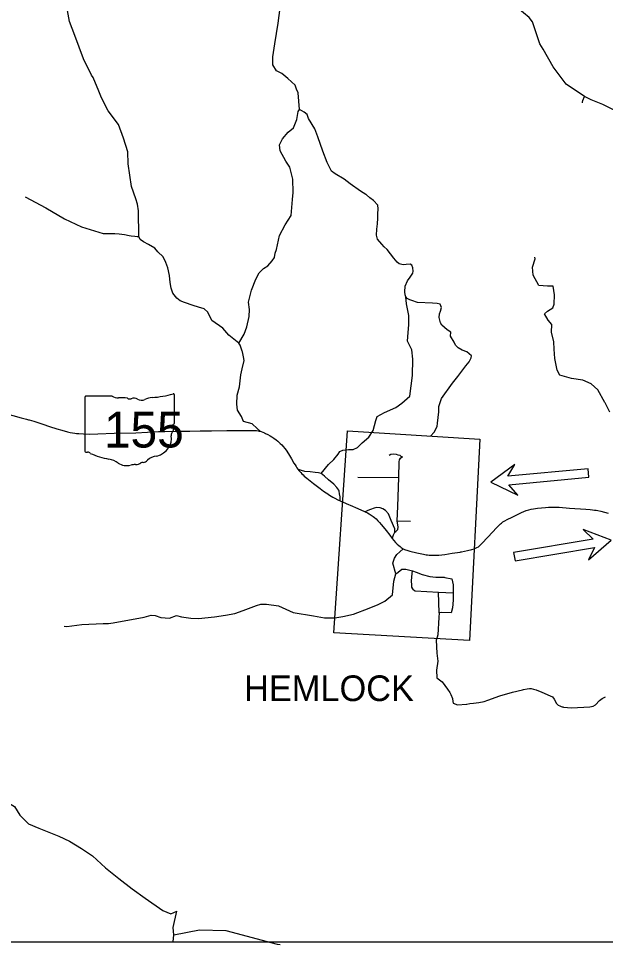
# Model space of a CAD drawing. Extents: x 2025369 to 2161369, y 549489 to 637489.
# Drawn here: x 2058249 to 2069680, y 571509 to 589545 of the extents above; entities that cross this region are included whole.
import ezdxf

# ---------------------------------------------------------------- set-up
doc = ezdxf.new("R2010")
doc.units = 0
for name, color, linetype in [('GM_X_City_Street', 7, 'Continuous'), ('GM_X_Corporation', 7, 'Continuous'), ('GM_X_Corporation_Text', 7, 'Continuous'), ('GM_X_County_Road', 7, 'Continuous'), ('GM_X_State_Route', 7, 'Continuous'), ('GM_X_State_Shield', 7, 'Continuous'), ('GM_X_Township_Road', 7, 'Continuous'), ('SH_Text', 7, 'Continuous')]:
    doc.layers.add(name, color=color, linetype=linetype)

msp = doc.modelspace()

# ---------------------------------------------------------------- linework, layer by layer
at = {"layer": 'GM_X_City_Street'}
for points in [[(2065470, 581041), (2065501, 581059), (2065553, 581067), (2065603, 581060), (2065639, 581048), (2065674, 581037), (2065696, 581020), (2065724, 581012)], [(2065581, 579541), (2065597, 579556), (2065616, 579571), (2065635, 579594), (2065644, 579640), (2065624, 579761), (2065636, 580039), (2065654, 580608), (2065664, 580911), (2065666, 580951), (2065685, 580983), (2065724, 581012)], [(2064854, 580610), (2065654, 580608)], [(2065529, 579415), (2065539, 579452), (2065553, 579489), (2065566, 579516), (2065581, 579541), (2065577, 579607), (2065505, 579770), (2065455, 579895), (2065393, 579960), (2065343, 579995), (2065294, 580016), (2065230, 580020), (2065178, 580008), (2065107, 579983), (2065051, 579962), (2065002, 579938)], [(2065624, 579761), (2065884, 579755)], [(2065600, 578731), (2065538, 578936), (2065572, 579033), (2065616, 579106), (2065677, 579159), (2065741, 579218)], [(2065941, 578415), (2065930, 578438), (2065908, 578472), (2065907, 578514), (2065901, 578584), (2065907, 578672), (2065922, 578787)], [(2063033, 578136), (2063078, 578137), (2063313, 578103), (2063599, 577974), (2063991, 577913), (2064208, 577871), (2064410, 577872), (2064568, 577895), (2064772, 577944), (2065081, 578062), (2065252, 578128), (2065382, 578196), (2065534, 578320), (2065556, 578586), (2065600, 578731), (2065641, 578761)], [(2065941, 578415), (2065973, 578400), (2066426, 578374), (2066714, 578358)], [(2066442, 577971), (2066426, 578374)]]:
    msp.add_lwpolyline(points, dxfattribs=at)
at = {"layer": 'GM_X_Corporation'}
msp.add_lwpolyline([(2067029, 577429), (2064390, 577577), (2064657, 581513), (2067234, 581349)], close=True, dxfattribs=at)
at = {"layer": 'GM_X_County_Road'}
for points in [[(2065023, 586109), (2065015, 586116), (2064907, 586180), (2064709, 586322), (2064594, 586415), (2064417, 586523), (2064343, 586574), (2064259, 586741), (2064178, 586962), (2064077, 587239), (2064018, 587398), (2063895, 587597), (2063873, 587677), (2063810, 587722), (2063724, 587773), (2063695, 588098), (2063661, 588166), (2063640, 588247), (2063491, 588374), (2063376, 588471), (2063272, 588526), (2063204, 588644), (2063204, 588796), (2063238, 589049), (2063306, 589454), (2063373, 589960)], [(2062629, 582957), (2062610, 583053), (2062605, 583067), (2062567, 583184), (2062542, 583223), (2062347, 583375), (2062229, 583514), (2062014, 583662), (2061938, 583825), (2061865, 583890), (2061757, 583921), (2061653, 583957), (2061484, 584011), (2061398, 584048), (2061331, 584099), (2061256, 584195), (2061225, 584296), (2061200, 584402), (2061188, 584538), (2061159, 584692), (2061121, 584795), (2061066, 584905), (2060965, 585001), (2060905, 585069), (2060782, 585141), (2060683, 585196), (2060617, 585241), (2060592, 585299), (2060587, 585797), (2060569, 585926), (2060531, 586030), (2060452, 586275), (2060383, 586716), (2060380, 586951), (2060293, 587215), (2060197, 587482), (2059996, 587746), (2059868, 587998), (2059812, 588131), (2059700, 588394), (2059672, 588441), (2059516, 588761), (2059345, 589213), (2059245, 589485), (2059188, 589770)], [(2065873, 584066), (2065818, 584090), (2065789, 584122), (2065779, 584162), (2065774, 584224), (2065781, 584334), (2065826, 584433), (2065875, 584505), (2065926, 584582), (2065938, 584626), (2065927, 584688), (2065912, 584742), (2065878, 584758), (2065798, 584757), (2065742, 584750), (2065660, 584765), (2065622, 584798), (2065557, 584880), (2065431, 585046), (2065373, 585100), (2065322, 585153), (2065243, 585246), (2065222, 585324), (2065227, 585440), (2065242, 585544), (2065248, 585656), (2065249, 585744), (2065250, 585840), (2065244, 585910), (2065165, 585998), (2065088, 586053), (2065023, 586109), (2065023, 586109)], [(2066274, 581409), (2066343, 581485), (2066402, 581600), (2066407, 581662), (2066424, 581773), (2066434, 581883), (2066435, 581989), (2066489, 582144), (2066700, 582442), (2066806, 582573), (2066963, 582777), (2067025, 582861), (2067066, 582936), (2067068, 582977), (2067025, 583016), (2066978, 583050), (2066888, 583087), (2066811, 583132), (2066759, 583183), (2066735, 583239), (2066663, 583356), (2066671, 583435), (2066598, 583484), (2066495, 583571), (2066467, 583620), (2066441, 583720), (2066449, 583794), (2066466, 583848), (2066487, 583919), (2066458, 583982), (2066400, 583994), (2066314, 583999), (2066022, 584013), (2065910, 584050), (2065873, 584066), (2065873, 584066)], [(2062955, 581505), (2062900, 581559), (2062799, 581648), (2062632, 581694), (2062590, 581790), (2062513, 581917), (2062502, 582031), (2062510, 582211), (2062554, 582373), (2062577, 582604), (2062606, 582724), (2062644, 582885), (2062629, 582957)]]:
    msp.add_lwpolyline(points, dxfattribs=at)
at = {"layer": 'GM_X_State_Route'}
for points in [[(2056230, 582726), (2056276, 582709), (2056331, 582686), (2056409, 582653), (2056462, 582629), (2056530, 582596), (2056654, 582529), (2056849, 582418), (2057041, 582307), (2057134, 582255), (2057219, 582208), (2057296, 582170), (2057415, 582111), (2057585, 582031), (2057679, 581986), (2057759, 581949), (2057830, 581915), (2057915, 581881), (2058018, 581845), (2058138, 581811), (2058303, 581768), (2058404, 581742), (2058445, 581731), (2058458, 581728)], [(2058458, 581728), (2058500, 581715), (2058550, 581699), (2058720, 581643), (2058853, 581601), (2058998, 581556), (2059096, 581528), (2059203, 581497), (2059257, 581482), (2059299, 581474), (2059343, 581467), (2059377, 581464), (2059427, 581460), (2059518, 581455), (2059638, 581452), (2059793, 581453), (2060115, 581467), (2060536, 581474), (2060764, 581489), (2060866, 581494), (2060977, 581499), (2061100, 581503), (2061297, 581507), (2061584, 581510), (2061785, 581513), (2062005, 581516), (2062307, 581520), (2062621, 581523), (2062711, 581523), (2062791, 581523), (2062857, 581520), (2062885, 581519), (2062914, 581515), (2062937, 581510), (2062955, 581505), (2062977, 581498), (2063005, 581488), (2063040, 581472), (2063061, 581463), (2063104, 581442), (2063148, 581417), (2063180, 581397), (2063222, 581369), (2063265, 581339), (2063300, 581312), (2063345, 581270), (2063375, 581242), (2063403, 581212), (2063434, 581173), (2063462, 581137), (2063509, 581066), (2063567, 580971), (2063613, 580886), (2063636, 580849), (2063656, 580816), (2063672, 580790), (2063690, 580765), (2063712, 580737), (2063746, 580700), (2063768, 580677), (2063791, 580656), (2063815, 580634), (2063867, 580590), (2063997, 580486), (2064123, 580388), (2064189, 580340), (2064241, 580304)], [(2064241, 580304), (2064251, 580297), (2064305, 580262), (2064337, 580243), (2064368, 580225), (2064409, 580202), (2064469, 580172), (2064511, 580153), (2064561, 580130), (2064631, 580098), (2064756, 580046)], [(2064756, 580046), (2064810, 580023), (2064975, 579950), (2065002, 579938), (2065044, 579916), (2065080, 579895), (2065118, 579871), (2065155, 579844), (2065179, 579825), (2065212, 579797), (2065245, 579763), (2065280, 579727), (2065313, 579689), (2065349, 579646), (2065408, 579570), (2065479, 579479), (2065529, 579415), (2065561, 579375), (2065594, 579339), (2065626, 579308), (2065657, 579280), (2065681, 579260), (2065704, 579241), (2065723, 579228), (2065741, 579218), (2065768, 579205), (2065829, 579185), (2065869, 579173), (2066005, 579140), (2066138, 579112), (2066187, 579101), (2066215, 579097), (2066248, 579092), (2066281, 579090), (2066326, 579089), (2066377, 579091), (2066435, 579095), (2066549, 579108), (2066694, 579128), (2066847, 579152), (2066862, 579155)], [(2066862, 579155), (2066877, 579158), (2066991, 579181), (2067075, 579201), (2067124, 579215), (2067150, 579227), (2067174, 579239), (2067204, 579257), (2067233, 579280), (2067281, 579325), (2067486, 579546), (2067550, 579618), (2067577, 579646), (2067603, 579671), (2067633, 579701), (2067652, 579718), (2067680, 579740), (2067717, 579762), (2067763, 579785), (2067861, 579832), (2067982, 579893), (2068045, 579922), (2068090, 579943), (2068137, 579962), (2068187, 579976), (2068231, 579987), (2068278, 579996), (2068358, 580006), (2068433, 580014), (2068515, 580020), (2068569, 580024), (2068610, 580025)], [(2068610, 580025), (2068665, 580027), (2068778, 580024), (2068982, 580010), (2069296, 579988), (2069382, 579980), (2069427, 579976), (2069469, 579971), (2069498, 579967), (2069534, 579960), (2069587, 579950), (2069661, 579932), (2069732, 579912)]]:
    msp.add_lwpolyline(points, dxfattribs=at)
at = {"layer": 'GM_X_State_Shield'}
for p, q in [((2061284, 581663), (2061284, 582216)), ((2059544, 582171), (2059544, 581115)), ((2060071, 582190), (2059561, 582190)), ((2061284, 581663), (2061284, 581663))]:
    msp.add_line(p, q, dxfattribs=at)
for centre, major_axis, start_param, end_param in [((2060664, 583630), (1845, 0), 4.814394, 5.042369), ((2061265, 582218), (19.4, 0), 6.141152, 7.989035), ((2059564, 582174), (20.2, 0), 1.712693, 3.28349), ((2060192, 582312), (196, 0), 4.042523, 4.731795), ((2060257, 581596), (702, 0), 1.404758, 1.657858), ((2060416, 582179), (56.4, 0), 3.836095, 5.185415), ((2060499, 582057), (117, 0), 0.950623, 2.079405), ((2060651, 582224), (141, 0), 4.081561, 5.145723), ((2060900, 581867), (371, 0), 1.699011, 2.107814), ((2061354, 581432), (131, 0), 2.387724, 3.262537), ((2061280, 581622), (30, 0), 1.883978, 3.671073), ((2061089, 581553), (180, 0), 5.934695, 6.695948), ((2061264, 581661), (20.7, 0), 5.05454, 6.418171), ((2060768, 581361), (462, 0), 5.101752, 6.440018), ((2059564, 581112), (20.3, 0), 3.00124, 4.508301), ((2059567, 581220), (155, 0), 4.665946, 4.897461), ((2059599, 581054), (56, 0), 0.519207, 1.627899), ((2060306, 582003), (1333, 0), 4.195997, 4.488961), ((2059908, 580640), (417, 0), 0.823519, 1.323587), ((2060962, 580818), (253, 0), 1.647645, 2.488434), ((2060359, 581049), (265, 0), 4.026481, 4.996735), ((2060512, 580683), (217, 0), 1.495662, 1.94098), ((2060532, 580969), (141, 0), 4.691044, 5.507374), ((2060659, 580867), (39.7, 0), 1.147584, 2.315152), ((2060642, 581012), (149, 0), 4.937069, 5.64225)]:
    msp.add_ellipse(centre, major_axis=major_axis, ratio=0.8, start_param=start_param, end_param=end_param, dxfattribs=at)
at = {"layer": 'GM_X_Township_Road'}
for points in [[(2069859, 587754), (2069630, 587869), (2069403, 587959), (2069270, 588029), (2068917, 588266), (2068663, 588601), (2068467, 588951), (2068400, 589049), (2068258, 589479), (2068192, 589562), (2068084, 589655), (2067950, 589766), (2067861, 589870), (2067758, 590040), (2067719, 590105)], [(2069232, 587906), (2069234, 587914), (2069241, 587951), (2069270, 588029)], [(2062542, 583223), (2062646, 583397), (2062693, 583538), (2062744, 583739), (2062747, 583877), (2062727, 584023), (2062788, 584251), (2062874, 584465), (2062938, 584589), (2063023, 584673), (2063107, 584726), (2063190, 584823), (2063233, 584891), (2063248, 584977), (2063271, 585048), (2063332, 585321), (2063445, 585528), (2063559, 585708), (2063582, 586018), (2063598, 586154), (2063593, 586414), (2063532, 586650), (2063453, 586765), (2063345, 586966), (2063332, 587088), (2063390, 587200), (2063499, 587334), (2063602, 587417), (2063670, 587578), (2063698, 587734), (2063724, 587773)], [(2058378, 586071), (2058783, 585857), (2059145, 585643), (2059479, 585485), (2059896, 585359), (2060036, 585360), (2060122, 585357), (2060210, 585352), (2060312, 585340), (2060406, 585321), (2060444, 585313), (2060512, 585308), (2060560, 585297), (2060592, 585299)], [(2069762, 581880), (2069672, 582057), (2069668, 582065), (2069533, 582311), (2069398, 582428), (2069239, 582500), (2069015, 582533), (2068788, 582600), (2068741, 582698), (2068695, 582921), (2068683, 583103), (2068675, 583245), (2068629, 583433), (2068633, 583583), (2068566, 583670), (2068493, 583793), (2068552, 583846), (2068656, 583907), (2068679, 583982), (2068689, 584166), (2068663, 584332), (2068549, 584334), (2068379, 584344), (2068271, 584543), (2068259, 584703), (2068311, 584866), (2068305, 584895)], [(2064142, 580680), (2064288, 580856), (2064390, 580957), (2064473, 581060), (2064507, 581109), (2064566, 581139), (2064678, 581149), (2064764, 581152), (2064850, 581187), (2064942, 581282), (2065071, 581392), (2065153, 581521), (2065211, 581714), (2065232, 581790), (2065377, 581872), (2065598, 581971), (2065711, 582050), (2065869, 582192), (2065921, 582589), (2065931, 582911), (2065907, 583093), (2065827, 583260), (2065839, 583428), (2065850, 583577), (2065851, 583761), (2065805, 583986), (2065789, 584122)], [(2064511, 580153), (2064514, 580230), (2064503, 580288), (2064493, 580340), (2064484, 580360), (2064470, 580383), (2064448, 580409), (2064393, 580472), (2064283, 580562), (2064210, 580629), (2064142, 580680), (2064090, 580695), (2064028, 580703), (2063932, 580713), (2063825, 580722), (2063757, 580743), (2063722, 580756), (2063690, 580765)], [(2065641, 578761), (2065717, 578817), (2065793, 578817), (2065922, 578787), (2065992, 578760), (2066107, 578713), (2066257, 578675), (2066377, 578664), (2066540, 578661), (2066551, 578660), (2066687, 578628), (2066714, 578514), (2066714, 578398), (2066714, 578358), (2066714, 578214), (2066700, 578066), (2066673, 577966), (2066495, 577977), (2066442, 577971), (2066434, 577875), (2066418, 577541), (2066402, 577496), (2066383, 577436), (2066396, 577184), (2066412, 577026), (2066392, 576850), (2066397, 576705), (2066501, 576624), (2066601, 576479), (2066646, 576418), (2066670, 576377), (2066700, 576299), (2066710, 576239), (2066712, 576207)], [(2060376, 577823), (2060696, 577882), (2060833, 577921), (2060908, 577914), (2061021, 577875), (2061188, 577864), (2061323, 577917), (2061423, 577894), (2061608, 577866), (2061759, 577861), (2061880, 577869), (2062068, 577888), (2062280, 577922), (2062460, 577957), (2062626, 578017), (2062881, 578111), (2062969, 578135), (2063033, 578136)], [(2059136, 577711), (2059193, 577705), (2059483, 577744), (2059899, 577758), (2060000, 577762), (2060092, 577776)], [(2060092, 577776), (2060340, 577817), (2060376, 577823)], [(2066973, 576190), (2066977, 576191), (2067041, 576206), (2067110, 576212), (2067215, 576221), (2067317, 576241), (2067390, 576269), (2067625, 576352), (2067867, 576423), (2068063, 576468), (2068086, 576477), (2068154, 576490), (2068199, 576493), (2068231, 576492), (2068275, 576485), (2068328, 576468), (2068439, 576426), (2068605, 576354), (2068647, 576330), (2068680, 576288), (2068727, 576200), (2068738, 576187), (2068749, 576178), (2068760, 576170), (2068789, 576156), (2068803, 576151), (2068818, 576145), (2068835, 576139), (2068847, 576137), (2068864, 576134), (2069016, 576121), (2069377, 576138), (2069440, 576148), (2069483, 576175), (2069564, 576258), (2069617, 576302), (2069681, 576334)], [(2066712, 576207), (2066797, 576179), (2066973, 576190)], [(2057956, 574307), (2058039, 574275), (2058170, 574199), (2058276, 574026), (2058444, 573856), (2058647, 573773), (2059036, 573621), (2059239, 573520), (2059474, 573381), (2059688, 573235), (2059944, 573004), (2060203, 572791), (2060461, 572592), (2060714, 572409), (2061057, 572171), (2061217, 572109), (2061330, 572155)], [(2061260, 571561), (2061274, 571699), (2061258, 571839), (2061330, 572155)], [(2061274, 571699), (2061773, 571794), (2062289, 571778), (2063286, 571518), (2063342, 571509)]]:
    msp.add_lwpolyline(points, dxfattribs=at)
at = {"layer": 'SH_Text'}
msp.add_lwpolyline([(2037369, 631489), (2037369, 571561), (2092420, 571561), (2092420, 631489)], dxfattribs=at)
for points in [[(2069358, 580610), (2069343, 580776), (2067779, 580628), (2067916, 580859), (2067446, 580513), (2067973, 580262), (2067795, 580463)], [(2067890, 579143), (2067918, 578979), (2069466, 579243), (2069347, 579002), (2069789, 579382), (2069246, 579594), (2069439, 579407)]]:
    msp.add_lwpolyline(points, close=True, dxfattribs=at)

# ---------------------------------------------------------------- texts
at = {"layer": 'GM_X_Corporation_Text'}
msp.add_text('HEMLOCK', height=500, rotation=0, dxfattribs=at).set_placement((2062643, 576250))
at = {"layer": 'GM_X_State_Shield'}
msp.add_text('155', height=696.1, dxfattribs=at).set_placement((2059913, 581189))

doc.saveas('drawing.dxf')
